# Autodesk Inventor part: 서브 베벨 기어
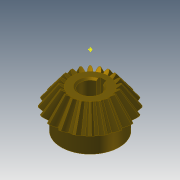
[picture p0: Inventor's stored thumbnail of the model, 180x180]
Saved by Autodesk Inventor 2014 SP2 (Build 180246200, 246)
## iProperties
Created: 2014-10
Part Number: 서브 베벨 기어
Material: Steel, Mild
Document SubType Name: Modeling
Designer: KYOUNG IL JANG
Categories: <?xml version="1.0" encoding="UTF-16"?> <MemberInstance><Categories><FamilyTemplate><FamilyTemplateParameter ValueType="xs:double" Id="1" ObjectReferenceKey="da
Mass: 134.866 g
Surface Area: 63.6518 cm^2
Volume: 17.1585 cm^3
Density: 7.86 g/cm^3
Appearance: 얼룩무늬
CustomPartVersion: 1
Company: 한국ATC센터
Author: KYOUNG IL JANG
Revision Number: 1
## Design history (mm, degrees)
node "맨 위 점"
node "메쉬 평면2"
sketch "톱니 본체 스케치"
  geometry: L1 (0, 0)-(18.003, -31.331); L2 (18.003, -31.331)-(21.664, -28.891); L3 (21.664, -28.891)-(0, 0); L4 (20, -30)-(0, 0); L5 (10.813, -18.818)-(13.012, -17.352); L6 (18.003, -31.331)-(10.813, -18.818); L7 (21.664, -28.891)-(13.012, -17.352); L8 (0, -39.387)-(0, 6.564) reference; L9 (0, -30)-(21.664, -30)
  constraints: 16 end point, 4 point on line, 3 perpendicular, 2 collinear, 1 horizontal alignment, 1 vertical alignment
  dimensions: "d0" = 40 diameter of L4.start L8 (= da_de); "d1" = 36.00616 diameter of L1.end L8 (= da_dfe); "d2" = 43.3282 diameter of L2.end L8 (= da_dae); "d3" = 14.4 distance between parallel lines of L2 L5 (= da_b); "d4" = 28.8906 vertical distance of L2.end L1.start (= da_ve)
revolve "톱니 본체" sketch "톱니 본체 스케치" stored, may be unused: angle "d5" = 90 deg
node "시작점"
node "톱니 평면"
sketch "시작 스케치"
  geometry: L1 (0, -23.505)-(0, 10.645) reference; L2 (-0.834, -2.928)-(0.834, -2.928); A1 r 8.898 centre (-9.698, -3.713) between (-0.834, -2.928) and (-3.903, 3.04); A2 r 8.898 centre (9.698, -3.713) between (3.903, 3.04) and (0.834, -2.928); A3 r 27.357 centre (0, -24.037) between (3.903, 3.04) and (-3.903, 3.04); 1 further point
  constraints: 6 point on circle, 3 centre point, 3 symmetric about line, 2 end point, 1 coincident, 1 perpendicular, 1 other
  dimensions: "d7" = 8.89846 radius of A1 (= fd_rr); "d8" = 9.69794 horizontal distance of point (0, -24.037) A1.centre (= fd_x); "d9" = 20.32439 vertical distance of point (0, -24.037) A1.centre (= fd_y); "d57" = 27.35701 radius of A3 (= 0.5 x fd_dva + 0.3 x da_he); "d58" = 21.10901 distance from line of A3.centre L2 (= 0.5 x fd_dva - 1.12 x da_he)
node "끝점"
  node "끝 평면"
sketch "3D 스케치 오른쪽"
  node "Helical Curve Right" dims "d65" = 229.90621 (computed from da_dm, da_delta, da_beta), "d66" = 31.5, "d67" = 40 (= da_de), "d68" = -5.88003 (= -da_delta), "d69" = 12.16458 (computed from fd_loft, da_delta)
node "끝 평면 오른쪽"
sketch "끝 스케치 오른쪽"
  geometry: L1 (0, -22.649)-(0, 12.15) reference; L2 (-0.497, -1.72)-(0.497, -1.72); A1 r 5.299 centre (-5.775, -2.187) between (-0.497, -1.72) and (-2.324, 1.834); A2 r 5.299 centre (5.775, -2.187) between (2.324, 1.834) and (0.497, -1.72); A3 r 16.291 centre (0, -14.29) between (2.324, 1.834) and (-2.324, 1.834); 1 further point
  constraints: 6 point on circle, 3 centre point, 3 symmetric about line, 2 end point, 1 coincident, 1 perpendicular, 1 other
  dimensions: "d70" = 5.77526 horizontal distance of A3.centre A1.centre (computed from fd_x, fd_ratio); "d71" = 12.10346 vertical distance of point (0, -14.29) A1.centre (computed from fd_y, fd_ratio); "d72" = 5.29916 radius of A1 (computed from fd_rr, fd_ratio); "d73" = 12.57071 distance from line of point (0, -14.29) L2 (computed from d58, fd_ratio); "d74" = 16.29149 radius of A3 (computed from d57, fd_ratio)
feature "로프트 오른쪽" sketch "끝 스케치 오른쪽" dims "d75" = 0, "d77" = 0, "d79" = 0, "d80" = 90 deg, "d85" = 20, "d92" = 90 deg, "d93" = 90 deg, "da_teethtype" = 0 [user parameter]
sketch "3D 스케치 왼쪽"
  node "Helical Curve Left" dims "d26" = 229.90621 (computed from da_dm, da_delta, da_beta), "d27" = 12.16458 (computed from fd_loft, da_delta), "d28" = 40 (= da_de), "d29" = -5.88003 (= -da_delta)
node "끝 평면 왼쪽"
sketch "끝 스케치 왼쪽" dims "d56" = 10.82768 (derived)
  geometry: L1 (0, -35.087)-(0, 18.089) reference; L2 (-0.497, -1.716)-(0.497, -1.716); A1 r 5.299 centre (-5.775, -2.183) between (-0.497, -1.716) and (-2.324, 1.838); A2 r 5.299 centre (5.775, -2.183) between (2.324, 1.838) and (0.497, -1.716); A3 r 16.291 centre (0, -14.287) between (2.324, 1.838) and (-2.324, 1.838); 2 further points; 1 other entity
  constraints: 6 point on circle, 3 centre point, 3 symmetric about line, 2 end point, 1 coincident, 2 other
  dimensions: "d30" = 5.29916 radius of A1 (computed from fd_rr, fd_ratio); "d31" = 5.77526 horizontal distance of point (0, -14.287) A1.centre (computed from fd_x, fd_ratio); "d32" = 12.10346 vertical distance of A1.centre point (0, -14.287) (computed from fd_y, fd_ratio); "d61" = 16.29149 radius of A3 (computed from d57, fd_ratio); "d62" = 12.57071 distance from line of point (0, -14.287) L2 (computed from d58, fd_ratio)
feature "로프트 왼쪽" sketch "끝 스케치 왼쪽" dims "d35" = 0, "d37" = 0, "d39" = 0, "d40" = 90 deg, "d84" = 10, "d90" = 90 deg, "d91" = 90 deg, "da_teethtype" = 0 [user parameter]
sketch "본체 스케치"
  geometry: L1 (0, -35.038)-(0, -19.531) reference; L2 (18.003, -31.331)-(10.813, -18.818) reference; L3 (10.813, -18.818)-(0, -18.818); L4 (18.003, -31.331)-(0, -31.331)
  constraints: 4 end point, 2 perpendicular, 2 point on line
revolve "본체 고정" sketch "본체 스케치" stored, may be unused: angle "d46" = 90 deg
feature "피치 지름" dims angle "d47" = 90 deg
sketch "스케치8"
  geometry: C1 r 17 at (0, 0); 1 further point
  constraints: 1 centre point, 1 coincident
  dimensions: "d94" = 34 diameter of C1
extrude "돌출1" join sketch "스케치8" distance "d95" = 10; taper "d96" = 0 deg
sketch "스케치9"
  geometry: 1 further point
hole "구멍1" sketch "스케치9" at (0, 0) diameter "d97" = 12; stored, may be unused: countersink angle "d101" = 90 deg, drill point angle "d103" = 118 deg; dims "d98" = 6, "d99" = 4, "d100" = 2, "d102" = 8
sketch "스케치10"
  geometry: 1 further point
sketch "스케치11"
  geometry: 1 further point
sketch "스케치12"
  geometry: L1 (-2, 5.657)-(-2, 7.8); L2 (-2, 7.8)-(2, 7.8); L3 (2, 7.8)-(2, 5.657); A1 r 6 centre (0, 0) between (-2, 5.657) and (2, 5.657) reference; 1 further point
  constraints: 6 end point, 2 parallel, 2 point on circle, 1 perpendicular, 1 vertical
  dimensions: "d104" = 4 distance of L1.end L2.end; "d105" = 13.8 dimension on A1 L2
extrude "돌출2" cut sketch "스케치12" stored distance "d106" = 7; taper "d107" = 0 deg
chamfer "모따기1" distance "d108" = 1; stored, may be unused: second distance "d109" = 2, angle "d110" = 45 deg
body "Solid1"
feature "로프트" dims "d17" = 0, "d18" = 90 deg, "d19" = 0, "d20" = 90 deg, "d89" = 0, "da_teethtype" = 0 [user parameter]
pattern_circular "원형 패턴" dims angle "d22" = 360 deg, "d88" = 0, "da_teethtype" = 0 [user parameter]
pattern_circular "원형 패턴 오른쪽" dims angle "d82" = 360 deg, "da_teethtype" = 0 [user parameter]
pattern_circular "원형 패턴 왼쪽" dims angle "d42" = 360 deg, "da_teethtype" = 0 [user parameter]
sketch "끝 스케치"
  geometry: L1 (0, -15.359)-(0, 6.983) reference; L2 (-0.497, -1.72)-(0.497, -1.72); A1 r 5.299 centre (-5.775, -2.187) between (-0.497, -1.72) and (-2.324, 1.834); A2 r 5.299 centre (5.775, -2.187) between (2.324, 1.834) and (0.497, -1.72); A3 r 16.291 centre (0, -14.29) between (2.324, 1.834) and (-2.324, 1.834); 1 further point
  constraints: 6 point on circle, 3 centre point, 3 symmetric about line, 2 end point, 1 coincident, 1 other
  dimensions: "d12" = 5.29916 radius of A1 (computed from fd_rr, fd_ratio); "d15" = 5.77526 horizontal distance of A1.centre point (0, -14.29) (computed from fd_x, fd_ratio); "d16" = 12.10346 vertical distance of A1.centre point (0, -14.29) (computed from fd_y, fd_ratio); "d59" = 16.29149 radius of A3 (computed from d57, fd_ratio); "d60" = 12.57071 distance from line of A3.centre L2 (computed from d58, fd_ratio)
sketch "Sketch6"
  geometry: L1 (20, -30)-(0, 0) reference; L2 (0, -37.8)-(0, 6.3) reference
body "Srf1"
other parameters: "da_b" = 14.4 [user parameter; used in 2 equation terms], "da_de" = 40 [user parameter; used in 4 equation terms], "da_dae" = 43.3282 [user parameter; used in 2 equation terms], "da_dfe" = 36.00616 [user parameter; used in 1 equation term], "da_le" = 36.05551 [user parameter; used in 1 equation term], "da_omega" = 90 deg [user parameter; used in 1 equation term], "da_beta" = 0 [user parameter; used in 2 equation terms], "da_delta" = 5.88003 [user parameter; used in 8 equation terms], "da_alpha" = 20 deg [user parameter; used in 2 equation terms], "da_he" = 4.4 [user parameter; used in 4 equation terms], "da_ve" = 28.8906 [user parameter; used in 1 equation term], "fd_dv" = 48.07402 (computed from da_de, da_delta) [user parameter; used in 1 equation term], "fd_dva" = 52.07402 (computed from da_dae, da_delta) [user parameter; used in 3 equation terms], "fd_dvb" = 45.1748 (computed from fd_dv, da_alpha) [user parameter; used in 2 equation terms], "da_zv" = 240.37008 [user parameter; used in 1 equation term], "fd_loft" = 14.62 (= da_b + 0.05 x da_he) [user parameter; used in 4 equation terms], "fd_ratio" = 5.95514 (computed from da_le, fd_loft) [user parameter; used in 15 equation terms], "fd_rr" = 8.89846 (computed from fd_dd, fd_dvb) [user parameter; used in 6 equation terms], "fd_angle" = 0.66075 (computed from da_zv) [user parameter; used in 4 equation terms], "fd_x1" = 1.58709 (computed from da_dvw, fd_angle) [user parameter; used in 1 equation term], "fd_y1" = 23.98456 (computed from da_dvw, fd_angle) [user parameter; used in 1 equation term], "fd_x2" = 8.11084 (computed from fd_rr, fd_angle2, fd_angle) [user parameter; used in 1 equation term], "fd_y2" = 3.66016 (computed from fd_rr, fd_angle2, fd_angle) [user parameter; used in 1 equation term], "fd_x" = 9.69794 (= fd_x1 + fd_x2) [user parameter; used in 4 equation terms], "fd_y" = 20.32439 (= fd_y1 - fd_y2) [user parameter; used in 4 equation terms], "fd_angle2" = 3.57832 (computed from fd_dvb, fd_dd, da_alpha) [user parameter; used in 2 equation terms], "fd_dd" = 48.55402 (= fd_dva - 0.8 x da_he) [user parameter; used in 2 equation terms], "da_dvw" = 48.07402 [user parameter; used in 2 equation terms], "d11" = 14.62 (= fd_loft), "da_dm" = 32.01232 [user parameter; used in 2 equation terms], "da_x" = 0 [user parameter], "da_m" = 2 [user parameter], "d48" = 0, "d49" = 0, "d50" = 90 deg (= da_omega), "d51" = 9 deg (computed from da_z), "d52" = 0, "d53" = 0, "d54" = 0
